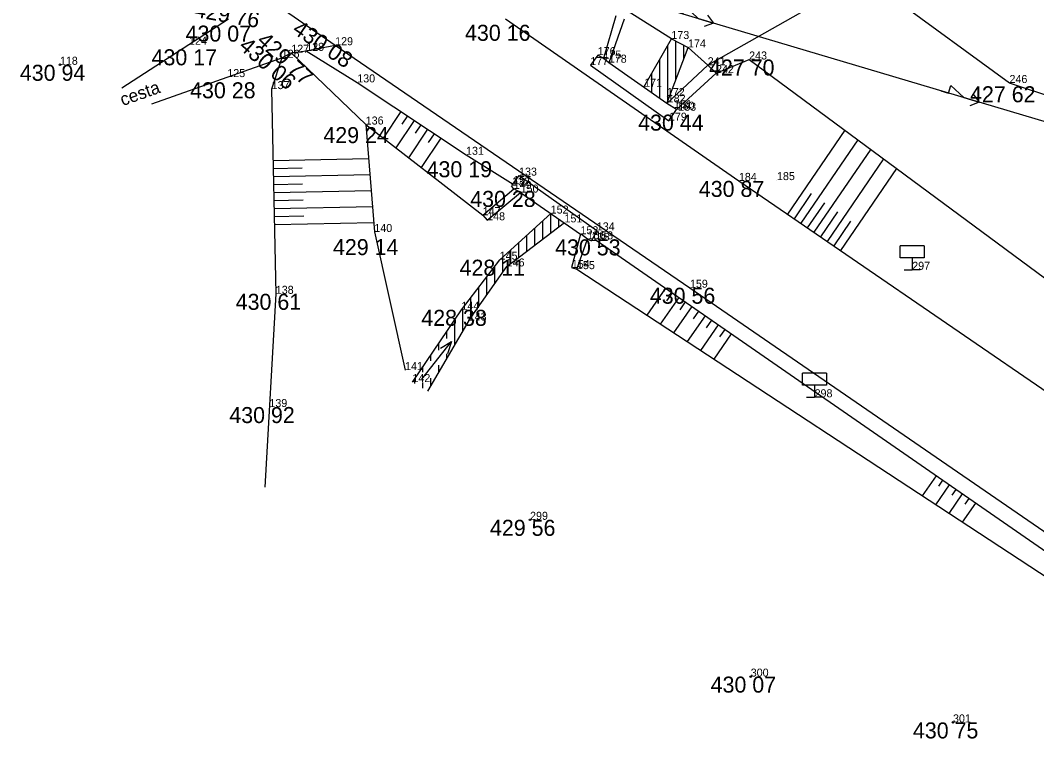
# Model space of a CAD drawing. Extents: x -559180 to -551373, y -1076947 to -1072071.
# Drawn here: x -554362.5 to -554299, y -1073834.5 to -1073789.7 of the extents above; entities that cross this region are included whole.
import ezdxf

# ---------------------------------------------------------------- set-up
doc = ezdxf.new("R2010")
doc.units = 0
for name, color, linetype in [('12_PLOTY', 7, 'Continuous'), ('17_KOMUNIKACE', 7, 'Continuous'), ('18_POLOHOPIS', 7, 'Continuous'), ('1_VODA_ZN', 7, 'Continuous'), ('20_EL_ZN', 7, 'Continuous'), ('26_SRAFY', 7, 'Continuous'), ('27_HRANA_PATA', 7, 'Continuous'), ('28_VODA', 7, 'Continuous'), ('32', 7, 'Continuous'), ('3_BODY', 7, 'Continuous'), ('48_DOPRAVA_ZN', 7, 'Continuous'), ('52_POPIS_UCELOVY', 7, 'Continuous'), ('6_VYSKY', 7, 'Continuous'), ('NNnadzemní', 7, 'Continuous')]:
    doc.layers.add(name, color=color, linetype=linetype)

# ---------------------------------------------------------------- blocks, each defined once
blk = doc.blocks.new('T')
at = {"layer": '6_VYSKY'}
blk.add_circle((0, 0), 0.05, dxfattribs=at)
blk = doc.blocks.new('MT')
at = {"layer": '48_DOPRAVA_ZN'}
for p, q in [((-0.75, 0.75), (-0.75, 1.5)), ((0.75, 1.5), (-0.75, 1.5)), ((0.75, 1.5), (0.75, 0.75)), ((0.75, 0.75), (-0.75, 0.75)), ((0, 0.75), (0, 0)), ((-0.5, 0), (0, 0)), ((0.5, 0), (0, 0))]:
    blk.add_line(p, q, dxfattribs=at)
blk = doc.blocks.new('VOTOK')
at = {"layer": '28_VODA'}
for p, q in [((-3, 0), (0, 0)), ((-0.75, 0.281), (0, 0)), ((0, 0), (-0.75, -0.281))]:
    blk.add_line(p, q, dxfattribs=at)
blk = doc.blocks.new('POINT_DISPLAY')
blk.add_line((0, 0), (0, 0))
blk = doc.blocks.new('ELNN')
at = {"layer": '20_EL_ZN'}
for p, q in [((0, 0), (0.5, 0)), ((0.5, 0), (0.5, 0.5)), ((0.5, 0.5), (1.5, 0)), ((1.5, 0), (2.5, 0))]:
    blk.add_line(p, q, dxfattribs=at)
blk.add_lwpolyline([(2, 0.375), (2.5, 0), (2, -0.375)], dxfattribs=at)

msp = doc.modelspace()

# ---------------------------------------------------------------- linework, layer by layer
at = {"layer": '12_PLOTY'}
for p, q in [((-554300.66, -1073793.57), (-554310.55, -1073786.33)), ((-554321.79, -1073790.82), (-554327.47, -1073787.17)), ((-554312.9, -1073788.73), (-554319.52, -1073792.46)), ((-554321.79, -1073790.82), (-554320.75, -1073791.35)), ((-554320.75, -1073791.35), (-554319.52, -1073792.46)), ((-554296.89, -1073794.82), (-554300.66, -1073793.57))]:
    msp.add_line(p, q, dxfattribs=at)
at = {"layer": '17_KOMUNIKACE'}
for p, q in [((-554349.44, -1073786.6), (-554342.8, -1073791.21)), ((-554349.46, -1073789.58), (-554356.126, -1073793.898)), ((-554332.16, -1073789.57), (-554317.57, -1073799.68)), ((-554344.61, -1073791.56), (-554342.8, -1073791.21)), ((-554342.8, -1073791.21), (-554320.63, -1073806.35)), ((-554346.14, -1073791.99), (-554345.54, -1073791.68)), ((-554345.54, -1073791.68), (-554344.61, -1073791.56)), ((-554354.25, -1073794.876), (-554346.14, -1073791.99)), ((-554317.57, -1073799.68), (-554290.56, -1073818.17)), ((-554320.63, -1073806.35), (-554286.62, -1073829.73))]:
    msp.add_line(p, q, dxfattribs=at)
at = {"layer": '18_POLOHOPIS'}
for p, q in [((-554325.26, -1073789.38), (-554326.03, -1073792.04)), ((-554324.74, -1073789.58), (-554325.7, -1073792.3)), ((-554326.39, -1073791.83), (-554326.85, -1073792.45)), ((-554326.03, -1073792.04), (-554326.39, -1073791.83)), ((-554326.85, -1073792.45), (-554321.94, -1073795.92)), ((-554325.7, -1073792.3), (-554326.03, -1073792.04)), ((-554322.084, -1073794.84), (-554325.7, -1073792.3)), ((-554322.084, -1073794.84), (-554319.52, -1073792.46)), ((-554319.52, -1073792.46), (-554319, -1073792.95)), ((-554321.46, -1073795.23), (-554319, -1073792.95)), ((-554321.46, -1073795.23), (-554322.084, -1073794.84)), ((-554321.94, -1073795.92), (-554321.46, -1073795.23)), ((-554331.75, -1073799.97), (-554331.31, -1073799.35)), ((-554331.31, -1073799.35), (-554326.45, -1073802.77)), ((-554333.58, -1073801.82), (-554331.64, -1073800.18)), ((-554331.64, -1073800.18), (-554331.78, -1073800.001)), ((-554331.21, -1073800.41), (-554331.64, -1073800.18)), ((-554333.3, -1073802.14), (-554331.21, -1073800.41)), ((-554331.21, -1073800.41), (-554327.47, -1073803.01)), ((-554333.58, -1073801.82), (-554333.3, -1073802.14)), ((-554327.47, -1073803.01), (-554328.023, -1073805.085)), ((-554327.69, -1073805.19), (-554327.03, -1073803.32)), ((-554327.397, -1073803.031), (-554327.47, -1073803.01)), ((-554327.03, -1073803.32), (-554327.397, -1073803.031)), ((-554327.03, -1073803.32), (-554326.78, -1073803.43)), ((-554326.45, -1073802.77), (-554326.78, -1073803.43)), ((-554328.023, -1073805.085), (-554327.69, -1073805.19))]:
    msp.add_line(p, q, dxfattribs=at)
at = {"layer": '26_SRAFY'}
for p, q in [((-554339.789, -1073797.012), (-554338.684, -1073795.349)), ((-554338.605, -1073796.134), (-554338.267, -1073795.626)), ((-554338.996, -1073797.626), (-554337.851, -1073795.903)), ((-554337.784, -1073796.705), (-554337.434, -1073796.179)), ((-554338.204, -1073798.24), (-554337.018, -1073796.456)), ((-554337.411, -1073798.854), (-554336.185, -1073797.01)), ((-554336.963, -1073797.277), (-554336.602, -1073796.733)), ((-554310.945, -1073796.52), (-554314.532, -1073801.76)), ((-554310.14, -1073797.115), (-554313.706, -1073802.325)), ((-554309.335, -1073797.709), (-554312.881, -1073802.89)), ((-554340.718, -1073798.302), (-554346.679, -1073798.423)), ((-554344.872, -1073798.887), (-554346.669, -1073798.923)), ((-554308.53, -1073798.304), (-554312.056, -1073803.455)), ((-554307.725, -1073798.898), (-554311.231, -1073804.019)), ((-554340.638, -1073799.301), (-554346.659, -1073799.423)), ((-554344.833, -1073799.886), (-554346.648, -1073799.923)), ((-554340.557, -1073800.299), (-554346.638, -1073800.423)), ((-554313.046, -1073800.475), (-554314.119, -1073802.042)), ((-554344.795, -1073800.885), (-554346.628, -1073800.923)), ((-554340.477, -1073801.298), (-554346.618, -1073801.423)), ((-554312.227, -1073801.049), (-554313.294, -1073802.607)), ((-554344.756, -1073801.885), (-554346.608, -1073801.923)), ((-554311.408, -1073801.622), (-554312.469, -1073803.172)), ((-554340.396, -1073802.296), (-554346.598, -1073802.422)), ((-554310.589, -1073802.196), (-554311.644, -1073803.737)), ((-554323.299, -1073808.07), (-554322.134, -1073806.387)), ((-554322.462, -1073808.619), (-554321.312, -1073806.957)), ((-554322.07, -1073807.174), (-554321.723, -1073806.672)), ((-554321.626, -1073809.167), (-554320.49, -1073807.526)), ((-554321.244, -1073807.737), (-554320.901, -1073807.241)), ((-554320.417, -1073808.3), (-554320.079, -1073807.81)), ((-554320.789, -1073809.716), (-554319.667, -1073808.095)), ((-554319.591, -1073808.863), (-554319.256, -1073808.38)), ((-554319.953, -1073810.264), (-554318.845, -1073808.664)), ((-554318.764, -1073809.426), (-554318.434, -1073808.949)), ((-554319.116, -1073810.813), (-554318.023, -1073809.233)), ((-554306.102, -1073819.347), (-554305.231, -1073818.089)), ((-554305.079, -1073818.748), (-554304.82, -1073818.374)), ((-554305.266, -1073819.896), (-554304.409, -1073818.659)), ((-554304.429, -1073820.444), (-554303.587, -1073819.228)), ((-554304.253, -1073819.311), (-554303.998, -1073818.943)), ((-554303.593, -1073820.993), (-554302.765, -1073819.797)), ((-554303.426, -1073819.874), (-554303.176, -1073819.513))]:
    msp.add_line(p, q, dxfattribs=at)
at = {"layer": '27_HRANA_PATA'}
for p, q in [((-554345.54, -1073791.68), (-554340.89, -1073796.16)), ((-554344.61, -1073791.56), (-554341.42, -1073793.53)), ((-554346.14, -1073791.99), (-554346.77, -1073793.95)), ((-554319, -1073792.95), (-554316.93, -1073792.1)), ((-554316.93, -1073792.1), (-554294.1, -1073808.96)), ((-554341.42, -1073793.53), (-554334.62, -1073798.05)), ((-554346.77, -1073793.95), (-554346.51, -1073806.73)), ((-554340.89, -1073796.16), (-554340.35, -1073802.87)), ((-554340.89, -1073796.16), (-554333.58, -1073801.82)), ((-554334.62, -1073798.05), (-554331.67, -1073799.88)), ((-554340.35, -1073802.87), (-554338.43, -1073811.49)), ((-554326.55, -1073803.33), (-554287.97, -1073830.04)), ((-554327.69, -1073805.19), (-554288.47, -1073830.91)), ((-554346.51, -1073806.73), (-554347.192, -1073818.792))]:
    msp.add_line(p, q, dxfattribs=at)
at = {"layer": '28_VODA'}
for p, q in [((-554323.511, -1073793.837), (-554321.79, -1073790.82)), ((-554322.084, -1073794.84), (-554320.75, -1073791.35)), ((-554332.52, -1073804.6), (-554329.33, -1073801.72)), ((-554332.08, -1073805.02), (-554328.47, -1073802.27)), ((-554334.91, -1073807.73), (-554332.52, -1073804.6)), ((-554334.45, -1073808.4), (-554332.08, -1073805.02)), ((-554337.97, -1073812.24), (-554334.91, -1073807.73)), ((-554334.45, -1073808.4), (-554337.027, -1073812.799))]:
    msp.add_line(p, q, dxfattribs=at)
at = {"layer": '32'}
for p, q in [((-554322.011, -1073794.649), (-554322.011, -1073791.207)), ((-554321.511, -1073793.341), (-554321.511, -1073790.962)), ((-554321.011, -1073792.033), (-554321.011, -1073791.217)), ((-554322.511, -1073794.54), (-554322.511, -1073792.084)), ((-554323.011, -1073794.188), (-554323.011, -1073792.96)), ((-554329.33, -1073802.925), (-554329.33, -1073801.72)), ((-554328.83, -1073802.544), (-554328.83, -1073802.04)), ((-554330.33, -1073803.687), (-554330.33, -1073802.623)), ((-554329.83, -1073803.306), (-554329.83, -1073802.171)), ((-554330.83, -1073804.068), (-554330.83, -1073803.074)), ((-554331.83, -1073804.83), (-554331.83, -1073803.977)), ((-554331.33, -1073804.449), (-554331.33, -1073803.526)), ((-554332.33, -1073805.377), (-554332.33, -1073804.428)), ((-554332.83, -1073806.09), (-554332.83, -1073805.006)), ((-554333.33, -1073806.803), (-554333.33, -1073805.661)), ((-554333.83, -1073807.516), (-554333.83, -1073806.316)), ((-554334.33, -1073808.229), (-554334.33, -1073806.97)), ((-554334.83, -1073809.049), (-554334.83, -1073807.625)), ((-554335.33, -1073809.902), (-554335.33, -1073808.349)), ((-554335.83, -1073809.524), (-554335.83, -1073809.086)), ((-554336.33, -1073810.247), (-554336.33, -1073809.823)), ((-554336.83, -1073810.91), (-554336.83, -1073810.56)), ((-554335.83, -1073810.756), (-554335.83, -1073810.488)), ((-554337.33, -1073811.613), (-554337.33, -1073811.297)), ((-554336.33, -1073811.609), (-554336.33, -1073811.191)), ((-554337.83, -1073812.323), (-554337.83, -1073812.034)), ((-554336.83, -1073812.463), (-554336.83, -1073811.995)), ((-554337.33, -1073812.619), (-554337.33, -1073812.276))]:
    msp.add_line(p, q, dxfattribs=at)
at = {"layer": 'NNnadzemní'}
msp.add_line((-554295.79, -1073796.78), (-554328.104, -1073787.165), dxfattribs=at)

# ---------------------------------------------------------------- block references
at = {"layer": '1_VODA_ZN'}
for p in [(-554351.93, -1073791.18), (-554342.8, -1073791.21), (-554321.79, -1073790.82), (-554345.54, -1073791.68), (-554344.61, -1073791.56), (-554326.39, -1073791.83), (-554320.75, -1073791.35), (-554360, -1073792.43), (-554346.14, -1073791.99), (-554326.85, -1073792.45), (-554326.03, -1073792.04), (-554325.7, -1073792.3), (-554319.52, -1073792.46), (-554316.93, -1073792.1), (-554349.54, -1073793.2), (-554319, -1073792.95), (-554341.42, -1073793.53), (-554323.49, -1073793.8), (-554300.66, -1073793.57), (-554346.77, -1073793.95), (-554322.07, -1073794.38), (-554322.02, -1073794.78), (-554321.62, -1073795.13), (-554321.46, -1073795.23), (-554321.36, -1073795.3), (-554340.89, -1073796.16), (-554321.94, -1073795.92), (-554334.62, -1073798.05), (-554331.31, -1073799.35), (-554331.75, -1073799.97), (-554331.67, -1073799.88), (-554331.64, -1073800.18), (-554317.57, -1073799.68), (-554315.19, -1073799.63), (-554331.21, -1073800.41), (-554333.58, -1073801.82), (-554329.33, -1073801.72), (-554333.3, -1073802.14), (-554328.47, -1073802.27), (-554340.35, -1073802.87), (-554327.47, -1073803.01), (-554327.03, -1073803.32), (-554326.55, -1073803.33), (-554326.45, -1073802.77), (-554326.78, -1073803.43), (-554332.52, -1073804.6), (-554332.08, -1073805.02), (-554328.01, -1073805.12), (-554327.69, -1073805.19), (-554306.74, -1073805.23), (-554320.63, -1073806.35), (-554346.51, -1073806.73), (-554334.91, -1073807.73), (-554334.45, -1073808.4), (-554338.43, -1073811.49), (-554337.97, -1073812.24), (-554312.84, -1073813.19), (-554346.91, -1073813.8), (-554330.62, -1073820.84), (-554316.83, -1073830.63), (-554304.19, -1073833.49)]:
    msp.add_blockref('POINT_DISPLAY', p, dxfattribs=at)
at = {"layer": '20_EL_ZN', "xscale": 1.0000012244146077, "yscale": 1.0000012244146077, "rotation": -16.57019023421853}
for p in [(-554321.553, -1073789.114), (-554304.951, -1073794.054)]:
    msp.add_blockref('ELNN', p, dxfattribs=at)
at = {"layer": '28_VODA', "xscale": 1.0000000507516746, "yscale": 1.0000000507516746, "rotation": 51.80983584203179}
msp.add_blockref('VOTOK', (-554335.537, -1073809.708), dxfattribs=at)
at = {"layer": '48_DOPRAVA_ZN'}
for p in [(-554306.74, -1073805.23), (-554312.84, -1073813.19)]:
    msp.add_blockref('MT', p, dxfattribs=at)
at = {"layer": '6_VYSKY'}
for p in [(-554360, -1073792.43), (-554360, -1073792.43), (-554330.62, -1073820.84), (-554330.62, -1073820.84), (-554316.83, -1073830.63), (-554316.83, -1073830.63), (-554304.19, -1073833.49), (-554304.19, -1073833.49)]:
    msp.add_blockref('T', p, dxfattribs=at)

# ---------------------------------------------------------------- texts
at = {"layer": '3_BODY'}
for s, p in [('124', (-554351.93, -1073791.18)), ('173', (-554321.79, -1073790.82)), ('127', (-554345.54, -1073791.68)), ('128', (-554344.61, -1073791.56)), ('129', (-554342.8, -1073791.21)), ('174', (-554320.75, -1073791.35)), ('118', (-554360, -1073792.43)), ('126', (-554346.14, -1073791.99)), ('176', (-554326.39, -1073791.83)), ('175', (-554326.03, -1073792.04)), ('178', (-554325.7, -1073792.3)), ('243', (-554316.93, -1073792.1)), ('177', (-554326.85, -1073792.45)), ('241', (-554319.52, -1073792.46)), ('242', (-554319, -1073792.95)), ('125', (-554349.54, -1073793.2)), ('130', (-554341.42, -1073793.53)), ('246', (-554300.66, -1073793.57)), ('137', (-554346.77, -1073793.95)), ('171', (-554323.49, -1073793.8)), ('172', (-554322.07, -1073794.38)), ('182', (-554322.02, -1073794.78)), ('181', (-554321.62, -1073795.13)), ('180', (-554321.46, -1073795.23)), ('183', (-554321.36, -1073795.3)), ('136', (-554340.89, -1073796.16)), ('179', (-554321.94, -1073795.92)), ('131', (-554334.62, -1073798.05)), ('133', (-554331.31, -1073799.35)), ('132', (-554331.75, -1073799.97)), ('157', (-554331.67, -1073799.88)), ('184', (-554317.57, -1073799.68)), ('185', (-554315.19, -1073799.63)), ('149', (-554331.64, -1073800.18)), ('150', (-554331.21, -1073800.41)), ('147', (-554333.58, -1073801.82)), ('152', (-554329.33, -1073801.72)), ('148', (-554333.3, -1073802.14)), ('151', (-554328.47, -1073802.27)), ('140', (-554340.35, -1073802.87)), ('153', (-554327.47, -1073803.01)), ('134', (-554326.45, -1073802.77)), ('156', (-554327.03, -1073803.32)), ('135', (-554326.78, -1073803.43)), ('158', (-554326.55, -1073803.33)), ('145', (-554332.52, -1073804.6)), ('146', (-554332.08, -1073805.02)), ('154', (-554328.01, -1073805.12)), ('155', (-554327.69, -1073805.19)), ('297', (-554306.74, -1073805.23)), ('159', (-554320.63, -1073806.35)), ('138', (-554346.51, -1073806.73)), ('144', (-554334.91, -1073807.73)), ('143', (-554334.45, -1073808.4)), ('141', (-554338.43, -1073811.49)), ('142', (-554337.97, -1073812.24)), ('298', (-554312.84, -1073813.19)), ('139', (-554346.91, -1073813.8)), ('299', (-554330.62, -1073820.84)), ('300', (-554316.83, -1073830.63)), ('301', (-554304.19, -1073833.49))]:
    msp.add_text(s, height=0.5, dxfattribs=at).set_placement(p)
at = {"layer": '52_POPIS_UCELOVY'}
msp.add_text('cesta', height=0.8, rotation=19.58846, dxfattribs=at).set_placement((-554356.072, -1073795.013))
at = {"layer": '6_VYSKY'}
for s, rotation, p in [('429 76', 350.0642, (-554351.653, -1073789.435)), ('430 08', 325.95484, (-554345.541, -1073790.4)), ('429 77', 317.36935, (-554347.764, -1073791.022)), ('430 06', 318.81636, (-554348.878, -1073791.368))]:
    msp.add_text(s, height=1, rotation=rotation, dxfattribs=at).set_placement(p)
for s, p in [('430 07', (-554352.147, -1073790.984)), ('430 16', (-554334.685, -1073790.933)), ('430 17', (-554354.273, -1073792.463)), ('430 94', (-554362.505, -1073793.43)), ('427 70', (-554319.435, -1073793.1)), ('430 28', (-554351.864, -1073794.523)), ('427 62', (-554303.125, -1073794.772)), ('430 44', (-554323.865, -1073796.542)), ('429 24', (-554343.536, -1073797.322)), ('430 19', (-554337.085, -1073799.453)), ('430 87', (-554320.075, -1073800.68)), ('430 28', (-554334.357, -1073801.304)), ('429 14', (-554342.936, -1073804.314)), ('430 53', (-554329.055, -1073804.33)), ('428 11', (-554335.025, -1073805.6)), ('430 56', (-554323.135, -1073807.35)), ('430 61', (-554349.015, -1073807.73)), ('428 38', (-554337.415, -1073808.73)), ('430 92', (-554349.415, -1073814.8)), ('429 56', (-554333.125, -1073821.84)), ('430 07', (-554319.335, -1073831.63)), ('430 75', (-554306.695, -1073834.49))]:
    msp.add_text(s, height=1, dxfattribs=at).set_placement(p)

doc.saveas('drawing.dxf')
